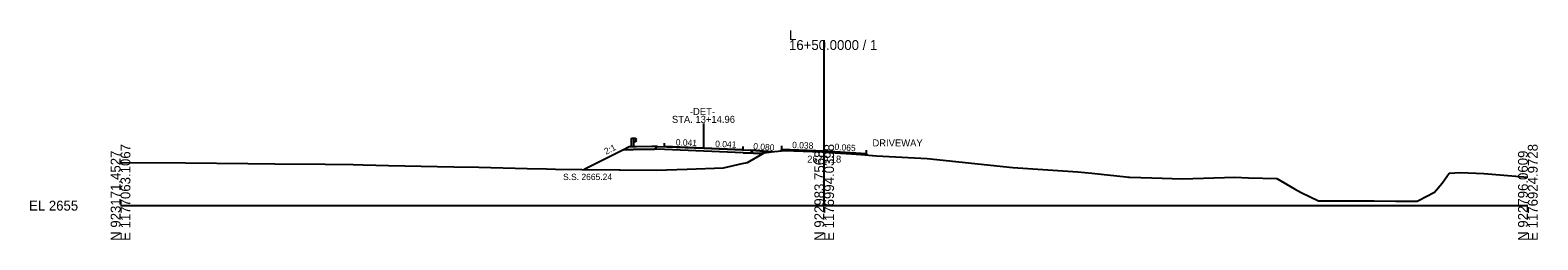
# Model space of a CAD drawing. Extents: x -26 to 1403, y -10 to 9563.
# Drawn here: x -25.7 to 402.8, y 6490.3 to 6549.8 of the extents above; entities that cross this region are included whole.
import ezdxf

# ---------------------------------------------------------------- set-up
doc = ezdxf.new("R2010")
doc.units = 0
for name, color, linetype in [('Exist Cross Section Cell', 7, 'Continuous'), ('Exist XS Center Line Elevation Label', 7, 'Continuous'), ('Exist XS Ground Line', 7, 'Continuous'), ('Prop XS Dump Level', 7, 'Continuous'), ('Prop XS Earthwork Shape', 7, 'Continuous'), ('Prop XS EOT Tick Mark', 7, 'Continuous'), ('Prop XS Finish Grade', 7, 'Continuous'), ('Prop XS Finish Grade Earthwork', 7, 'Continuous'), ('Prop XS Finish Grade Pavement', 7, 'Continuous'), ('Prop XS Guardrail', 7, 'Continuous'), ('Prop XS Pvmt Edge Slope', 7, 'Continuous'), ('Prop XS SE Text', 7, 'Continuous'), ('Prop XS Shoulder Borrow Shape', 7, 'Continuous'), ('Prop XS Side Slope Text', 7, 'Continuous'), ('Prop XS SS Elevation Text', 7, 'Continuous'), ('Prop XS Subgrade Earthwork', 7, 'Continuous'), ('Prop XS Vertical Lines', 7, 'Continuous'), ('Prop XS Wedging', 7, 'Continuous')]:
    doc.layers.add(name, color=color, linetype=linetype)

msp = doc.modelspace()

# ---------------------------------------------------------------- linework, layer by layer
at = {"layer": 'Exist Cross Section Cell'}
for p, q in [((200, 6500), (200, 6546.96)), ((0, 6500), (200, 6500)), ((200, 6500), (400, 6500))]:
    msp.add_line(p, q, dxfattribs=at)
at = {"layer": 'Exist XS Ground Line'}
for p, q in [((178.16, 6512.25), (182.43, 6514.67)), ((182.43, 6514.67), (183.09, 6515.05)), ((183.09, 6515.05), (185.87, 6515.34)), ((185.87, 6515.34), (188.94, 6515.65)), ((188.94, 6515.65), (191.34, 6515.55)), ((191.34, 6515.55), (199.36, 6515.22)), ((199.36, 6515.22), (200, 6515.18)), ((200, 6515.18), (207.79, 6514.71)), ((207.79, 6514.71), (210.4, 6514.55)), ((210.4, 6514.55), (214.86, 6514.17)), ((214.86, 6514.17), (229.29, 6513.34)), ((0, 6512.19), (18.48, 6512.14)), ((18.48, 6512.14), (36.17, 6511.92)), ((36.17, 6511.92), (43.86, 6511.83)), ((43.86, 6511.83), (58.19, 6511.73)), ((58.19, 6511.73), (66.1, 6511.65)), ((66.1, 6511.65), (68.98, 6511.55)), ((68.98, 6511.55), (76.15, 6511.43)), ((76.15, 6511.43), (94.75, 6511.02)), ((94.75, 6511.02), (101.81, 6510.9)), ((101.81, 6510.9), (115.62, 6510.53)), ((115.62, 6510.53), (121.06, 6510.39)), ((121.06, 6510.39), (123.59, 6510.36)), ((123.59, 6510.36), (131.07, 6510.24)), ((131.07, 6510.24), (152.23, 6510.1)), ((152.23, 6510.1), (161.07, 6510.31)), ((161.07, 6510.31), (171.41, 6510.71)), ((171.41, 6510.71), (176.72, 6511.92)), ((176.72, 6511.92), (178.16, 6512.25)), ((229.29, 6513.34), (253.59, 6510.85)), ((253.59, 6510.85), (272.08, 6509.6)), ((272.08, 6509.6), (276.07, 6509.24)), ((377.61, 6509.25), (380.83, 6509.44)), ((380.83, 6509.44), (387.49, 6509.14)), ((276.07, 6509.24), (285.81, 6508.13)), ((285.81, 6508.13), (286.46, 6508.05)), ((286.46, 6508.05), (286.91, 6508.05)), ((286.91, 6508.05), (293.14, 6507.87)), ((293.14, 6507.87), (301.85, 6507.64)), ((301.85, 6507.64), (316.69, 6508.07)), ((316.69, 6508.07), (320.61, 6507.9)), ((320.61, 6507.9), (328.63, 6507.69)), ((328.63, 6507.69), (333.67, 6504.79)), ((373.44, 6503.79), (375.65, 6506.37)), ((375.65, 6506.37), (377.61, 6509.25)), ((387.49, 6509.14), (392.06, 6508.75)), ((392.06, 6508.75), (400, 6508.04)), ((333.67, 6504.79), (335.54, 6503.77)), ((335.54, 6503.77), (337.94, 6502.6)), ((337.94, 6502.6), (340.51, 6501.36)), ((340.51, 6501.36), (340.99, 6501.36)), ((340.99, 6501.36), (349.65, 6501.34)), ((349.65, 6501.34), (356.32, 6501.32)), ((356.32, 6501.32), (362.45, 6501.31)), ((362.45, 6501.31), (368.56, 6501.31)), ((368.56, 6501.31), (368.88, 6501.47)), ((368.88, 6501.47), (373.44, 6503.79))]:
    msp.add_line(p, q, dxfattribs=at)
at = {"layer": 'Prop XS Dump Level'}
for p, q in [((152.59, 6516.81), (165.79, 6516.28)), ((165.79, 6516.28), (154.59, 6516.73)), ((177, 6515.82), (165.79, 6516.28)), ((165.79, 6516.28), (179, 6515.74)), ((200, 6515.49), (188, 6515.94)), ((212, 6514.7), (200, 6515.49))]:
    msp.add_line(p, q, dxfattribs=at)
at = {"layer": 'Prop XS Earthwork Shape'}
for p, q in [((142.96, 6515.84), (131.76, 6510.24)), ((145.79, 6515.9), (142.96, 6515.84)), ((151.79, 6516.01), (145.79, 6515.9)), ((154.59, 6515.9), (151.79, 6516.01)), ((165.79, 6515.44), (154.59, 6515.9)), ((177, 6514.99), (165.79, 6515.44)), ((179.87, 6514.87), (177, 6514.99)), ((178.16, 6512.25), (182.43, 6514.67)), ((181.47, 6514.74), (179.87, 6514.87)), ((182.92, 6514.95), (181.47, 6514.74)), ((182.43, 6514.67), (182.92, 6514.95)), ((182.92, 6514.95), (185.04, 6515.25)), ((183.09, 6515.05), (182.92, 6514.95)), ((185.04, 6515.25), (183.09, 6515.05)), ((131.76, 6510.24), (152.23, 6510.1)), ((152.23, 6510.1), (161.07, 6510.31)), ((161.07, 6510.31), (171.41, 6510.71)), ((171.41, 6510.71), (176.72, 6511.92)), ((176.72, 6511.92), (178.16, 6512.25))]:
    msp.add_line(p, q, dxfattribs=at)
at = {"layer": 'Prop XS EOT Tick Mark'}
for p, q in [((154.59, 6516.73), (154.59, 6517.73)), ((177, 6515.82), (177, 6516.82)), ((188, 6515.94), (188, 6516.94)), ((212, 6514.7), (212, 6515.7))]:
    msp.add_line(p, q, dxfattribs=at)
at = {"layer": 'Prop XS Finish Grade'}
for p, q in [((152.59, 6516.81), (151.02, 6516.78)), ((179, 6515.74), (180.61, 6515.61)), ((188, 6515.94), (187.57, 6515.52)), ((212, 6514.7), (212.32, 6514.39))]:
    msp.add_line(p, q, dxfattribs=at)
at = {"layer": 'Prop XS Finish Grade Earthwork'}
for p, q in [((142.96, 6515.84), (131.76, 6510.24)), ((144.59, 6516.66), (142.96, 6515.84)), ((146.59, 6516.7), (144.59, 6516.66)), ((151.02, 6516.78), (146.59, 6516.7)), ((180.61, 6515.61), (185.04, 6515.25))]:
    msp.add_line(p, q, dxfattribs=at)
at = {"layer": 'Prop XS Finish Grade Pavement'}
for p, q in [((152.59, 6516.81), (165.79, 6516.28)), ((165.79, 6516.28), (179, 6515.74)), ((188, 6515.94), (200, 6515.49)), ((200, 6515.49), (212, 6514.7))]:
    msp.add_line(p, q, dxfattribs=at)
at = {"layer": 'Prop XS Guardrail'}
for p, q in [((145.27, 6519.18), (145.77, 6519.18)), ((145.27, 6516.68), (145.27, 6519.18)), ((145.77, 6519.18), (146.27, 6519.18)), ((145.77, 6519.18), (145.77, 6516.68)), ((146.27, 6518.05), (145.77, 6518.05)), ((146.27, 6519.18), (146.56, 6518.98)), ((146.56, 6518.86), (146.27, 6518.66)), ((146.27, 6518.66), (146.27, 6518.57)), ((146.27, 6518.57), (146.56, 6518.37)), ((146.56, 6518.25), (146.27, 6518.05)), ((146.56, 6518.98), (146.59, 6518.92)), ((146.59, 6518.92), (146.56, 6518.86)), ((146.56, 6518.37), (146.59, 6518.31)), ((146.59, 6518.31), (146.56, 6518.25))]:
    msp.add_line(p, q, dxfattribs=at)
at = {"layer": 'Prop XS Pvmt Edge Slope'}
for p, q in [((152.59, 6516.81), (151.79, 6516.01)), ((179, 6515.74), (179.87, 6514.87)), ((188, 6515.94), (187.77, 6515.71)), ((212, 6514.7), (212.23, 6514.48))]:
    msp.add_line(p, q, dxfattribs=at)
at = {"layer": 'Prop XS Shoulder Borrow Shape'}
for p, q in [((144.59, 6516.66), (142.96, 6515.84)), ((142.96, 6515.84), (145.79, 6515.9)), ((145.77, 6516.68), (144.59, 6516.66)), ((146.59, 6516.7), (145.77, 6516.68)), ((145.77, 6516.68), (145.77, 6516.68)), ((145.79, 6515.9), (151.79, 6516.01)), ((151.02, 6516.78), (146.59, 6516.7)), ((152.59, 6516.81), (151.02, 6516.78)), ((151.79, 6516.01), (152.59, 6516.81)), ((180.61, 6515.61), (179, 6515.74)), ((179, 6515.74), (179.87, 6514.87)), ((179.87, 6514.87), (181.47, 6514.74)), ((185.04, 6515.25), (180.61, 6515.61)), ((181.47, 6514.74), (182.92, 6514.95)), ((182.92, 6514.95), (183.09, 6515.05)), ((183.09, 6515.05), (185.04, 6515.25))]:
    msp.add_line(p, q, dxfattribs=at)
msp.add_lwpolyline([(145.77, 6516.68), (145.77, 6516.68)], dxfattribs=at)
at = {"layer": 'Prop XS Subgrade Earthwork'}
for p, q in [((145.79, 6515.9), (142.96, 6515.84)), ((151.79, 6516.01), (145.79, 6515.9)), ((154.59, 6515.9), (151.79, 6516.01)), ((165.79, 6515.44), (154.59, 6515.9)), ((177, 6514.99), (165.79, 6515.44)), ((177, 6514.99), (179.87, 6514.87)), ((179.87, 6514.87), (181.47, 6514.74)), ((181.47, 6514.74), (185.04, 6515.25))]:
    msp.add_line(p, q, dxfattribs=at)
at = {"layer": 'Prop XS Vertical Lines'}
msp.add_line((165.79, 6516.28), (165.79, 6523.28), dxfattribs=at)
at = {"layer": 'Prop XS Wedging'}
msp.add_lwpolyline([(188.94, 6515.65), (188.94, 6515.7), (191.34, 6515.61), (199.36, 6515.3), (200, 6515.28), (200.49, 6515.26), (207.79, 6514.75), (210.4, 6514.57), (210.4, 6514.55), (207.79, 6514.71), (200.49, 6515.15), (200, 6515.18), (199.36, 6515.22), (191.34, 6515.55)], close=True, dxfattribs=at)

# ---------------------------------------------------------------- texts
at = {"layer": 'Exist Cross Section Cell'}
for s, p in [('L', (190, 6546.96)), ('16+50.0000 / 1', (190, 6544.16)), ('EL 2655', (-26, 6498.6))]:
    msp.add_text(s, height=2.8, dxfattribs=at).set_placement(p)
for s, p in [('N 923171.4527', (0, 6490)), ('E 1177063.1067', (2.8, 6490)), ('N 922983.7568', (200, 6490)), ('E 1176994.0398', (202.8, 6490)), ('N 922796.0609', (400, 6490)), ('E 1176924.9728', (402.8, 6490))]:
    msp.add_text(s, height=2.8, rotation=90, dxfattribs=at).set_placement(p)
at = {"layer": 'Exist XS Center Line Elevation Label'}
msp.add_text('2670.18', height=2, dxfattribs=at).set_placement((195.17, 6512.18))
at = {"layer": 'Prop XS Dump Level'}
for s, height, p in [('Case1', 0.04, (146.59, 6516.54)), ('Case2', 0.04, (180, 6515.38)), ('Eop', 0.3, (178, 6512.14))]:
    msp.add_text(s, height=height, dxfattribs=at).set_placement(p)
at = {"layer": 'Prop XS SE Text'}
for s, rotation, p in [('0.041', 357.6699, (157.79, 6517.1)), ('0.041', 357.6651, (168.99, 6516.65)), ('0.038', 357.8238, (190.86, 6516.33)), ('0.080', 355.6724, (179.78, 6515.98)), ('0.065', 356.281, (202.88, 6515.8))]:
    msp.add_text(s, height=1.8, rotation=rotation, dxfattribs=at).set_placement(p)
at = {"layer": 'Prop XS Side Slope Text'}
msp.add_text('2:1', height=1.8, rotation=26.5651, dxfattribs=at).set_placement((138.02, 6514.42))
at = {"layer": 'Prop XS SS Elevation Text'}
msp.add_text('S.S. 2665.24', height=1.8, dxfattribs=at).set_placement((125.78, 6507.24))
at = {"layer": 'Prop XS Vertical Lines'}
for s, p in [('-DET-', (161.82, 6525.72)), ('STA. 13+14.96', (156.72, 6523.47)), ('DRIVEWAY', (213.72, 6516.79))]:
    msp.add_text(s, height=2, dxfattribs=at).set_placement(p)

doc.saveas('drawing.dxf')
